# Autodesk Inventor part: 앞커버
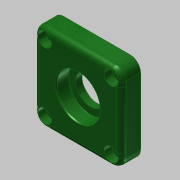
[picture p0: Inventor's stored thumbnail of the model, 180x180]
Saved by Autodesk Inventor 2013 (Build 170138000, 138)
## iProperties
Created: 2018-07
Part Number: 앞커버
Material: 알루미늄 6061
Document SubType Name: Modeling
Designer: mduedu
Density: 1 g/cm^3
Author: mduedu
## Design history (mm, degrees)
sketch "스케치1"
  geometry: C1 r 16 at (0, 0); 1 further point
  constraints: 1 centre point, 1 coincident
  dimensions: "d0" = 32 diameter of C1
extrude "돌출1" new body sketch "스케치1" distance "d1" = 3; taper "d2" = 0 deg
sketch "스케치2"
  geometry: L1 (-25, -25)-(25, -25); L2 (25, -25)-(25, 25); L3 (25, 25)-(-25, 25); L4 (-25, 25)-(-25, -25); L5 (-25, -25)-(25, 25); L6 (25, -25)-(-25, 25); 1 further point
  constraints: 12 end point, 2 midpoint, 2 parallel, 1 horizontal, 1 perpendicular
  dimensions: "d3" = 50 distance of L3.end L2.end; "d4" = 50 distance of L2.end L1.end
extrude "돌출2" join sketch "스케치2" distance "d5" = 11; taper "d6" = 0 deg
hole "구멍1" diameter "d9" = 25; stored, may be unused: countersink angle "d13" = 90 deg, drill point angle "d15" = 0 deg; dims "d7" = 10, "d8" = 10, "d10" = 6, "d11" = 4, "d12" = 2, "d14" = 3
sketch "스케치3"
  geometry: C1 r 12.5 at (0, 0); 1 further point
  constraints: 1 centre point, 1 coincident
  dimensions: "d16" = 25 diameter of C1
extrude "돌출3" cut sketch "스케치3" distance "d17" = 7.3; taper "d18" = 0 deg
sketch "스케치4"
  geometry: C1 r 8.5 at (0, 0); 1 further point
  constraints: 1 centre point, 1 coincident
  dimensions: "d19" = 17 diameter of C1
extrude "돌출4" cut sketch "스케치4" stored distance "d20" = 7.3; taper "d21" = 0 deg
chamfer "모따기1" distance "d22" = 0.7; stored, may be unused: second distance "d23" = 2, angle "d24" = 30 deg
fillet "모깎기1" dims "d25" = 0.3
fillet "모깎기2" dims "d26" = 3
fillet "모깎기3" dims "d27" = 6
sketch "스케치5"
  geometry: L1 (25, -19)-(25, 19) reference; L2 (19, 25)-(-19, 25) reference; L3 (-25, 19)-(-25, -19) reference; L4 (-19, -25)-(19, -25) reference; C1 r 12.904 at (0, 0) reference; A1 r 6 centre (19, -19) between (19, -25) and (25, -19) reference; A2 r 6 centre (19, 19) between (25, 19) and (19, 25) reference; A3 r 6 centre (-19, 19) between (-19, 25) and (-25, 19) reference; A4 r 6 centre (-19, -19) between (-25, -19) and (-19, -25) reference; 5 further points
  constraints: 4 coincident
hole "구멍2" sketch "스케치5" at (-19, 19), (19, 19), (19, -19), (-19, -19) diameter "d28" = 4.5; stored, may be unused: countersink angle "d32" = 90 deg, drill point angle "d34" = 0 deg; dims "d29" = 6, "d30" = 8, "d31" = 4.6, "d33" = 3
fillet "모깎기4" dims "d35" = 3
chamfer "모따기2" distance "d36" = 1; stored, may be unused: second distance "d37" = 2, angle "d38" = 45 deg
node "솔리드1"
node "투영된 루프1"
